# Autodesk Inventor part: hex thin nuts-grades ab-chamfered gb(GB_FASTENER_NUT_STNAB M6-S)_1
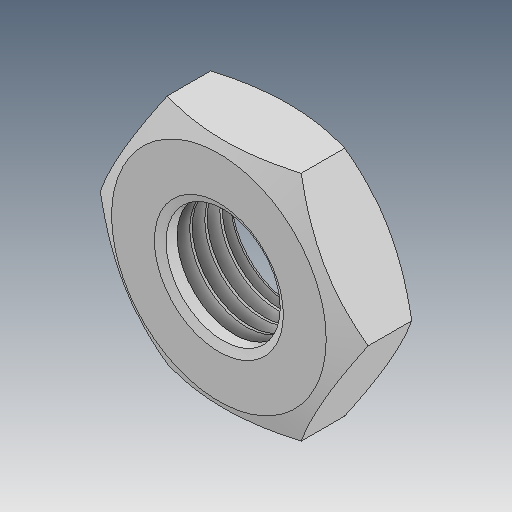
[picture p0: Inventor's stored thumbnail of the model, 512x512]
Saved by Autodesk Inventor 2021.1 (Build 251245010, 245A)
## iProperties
Created: 2019-12
Part Number: hex thin nuts-grades ab-chamfered gb(GB_FASTENER_NUT_STNAB M6-S)_1
Material: Ogólny
Document SubType Name: Modeling
Designer: user
Density: 1 g/cm^3
Appearance: Domyślna
Author: user
Revision Number: ÈÎºÎ
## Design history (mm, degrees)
feature "ÊäÈë1"
node "Bryła1"
